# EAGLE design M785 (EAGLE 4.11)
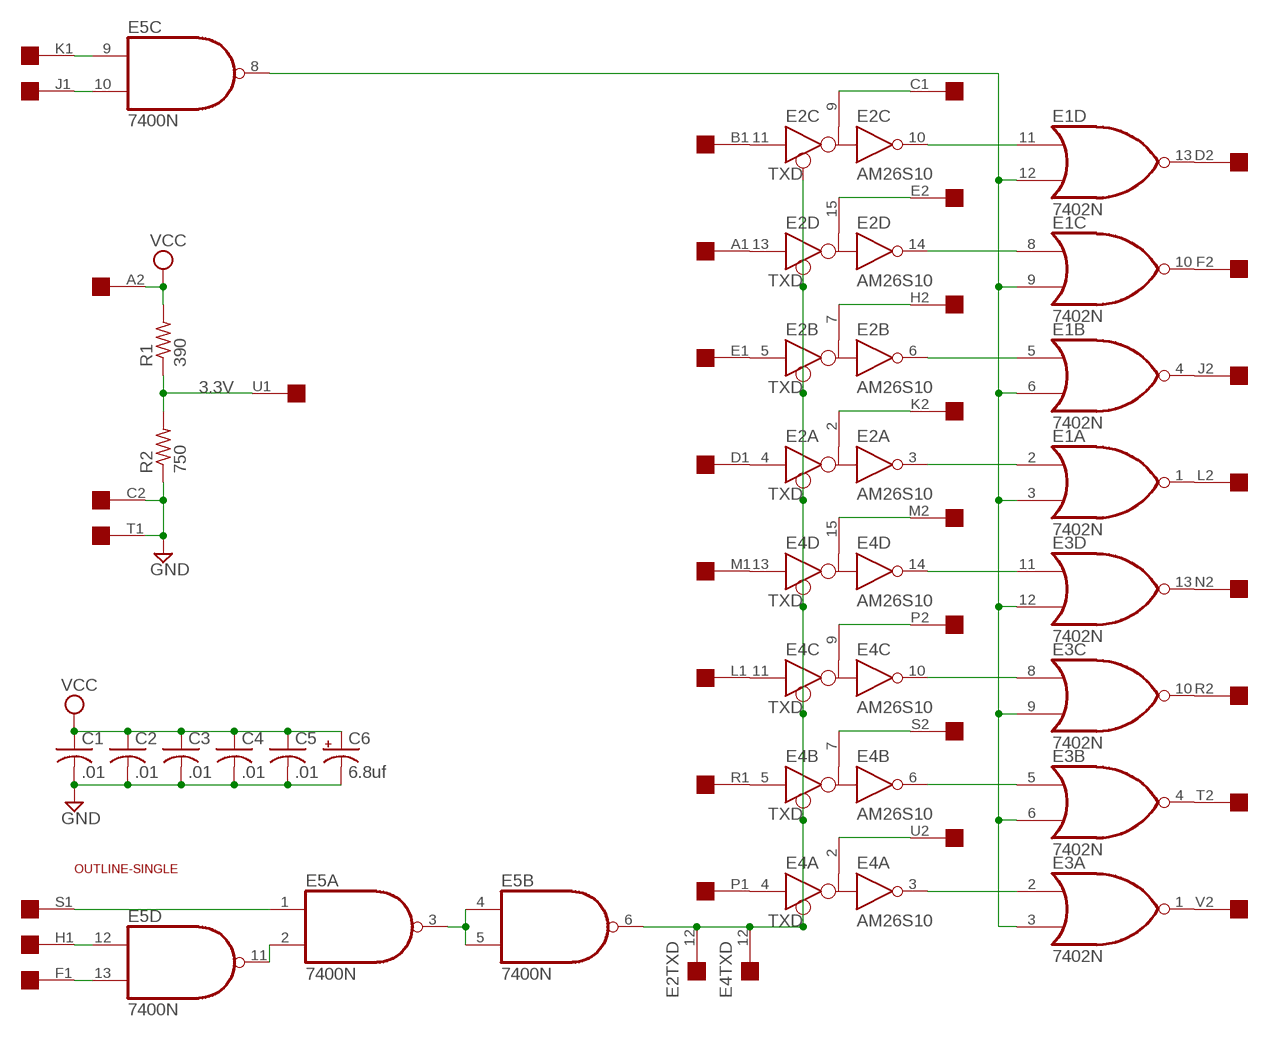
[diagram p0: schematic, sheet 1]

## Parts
C1  .01  C-US050-025X075  [C050-025X075]
C2  .01  C-US050-025X075  [C050-025X075]
C3  .01  C-US050-025X075  [C050-025X075]
C4  .01  C-US050-025X075  [C050-025X075]
C5  .01  C-US050-025X075  [C050-025X075]
C6  6.8uf  CPOL-USE15-5AXIAL  [E15-5]
E1  7402N  [DIL14]
E2  AM26S10  [DIL16]
E3  7402N  [DIL14]
E4  AM26S10  [DIL16]
E5  7400N  [DIL14]
R1  390  R-US_0207/10  [0207/10]
R2  750  R-US_0207/10  [0207/10]
U$1  SINGLE  [EDGE-CON2]
U$2  OUTLINE-SINGLE  [SINGLE]

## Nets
3.3V: R1.1 R2.2 U$1.U1
GND: C1.2 C2.2 C3.2 C4.2 C5.2 C6.- R2.1 U$1.C2 U$1.T1
N$2: E2.12(TXD:TXD) E4.12(TXD:TXD) E5.6(B:O)
N$3: E4.15(D:B) U$1.M2
N$4: E4.9(C:B) U$1.P2
N$5: E4.13(D:D) U$1.M1
N$6: E4.11(C:D) U$1.L1
N$7: E4.7(B:B) U$1.S2
N$8: E4.5(B:D) U$1.R1
N$9: E4.2(A:B) U$1.U2
N$10: E4.4(A:D) U$1.P1
N$11: E2.9(C:B) U$1.C1
N$12: E2.11(C:D) U$1.B1
N$13: E2.15(D:B) U$1.E2
N$14: E2.13(D:D) U$1.A1
N$15: E2.7(B:B) U$1.H2
N$16: E2.5(B:D) U$1.E1
N$17: E2.2(A:B) U$1.K2
N$18: E2.4(A:D) U$1.D1
N$19: E5.9(C:I0) U$1.K1
N$20: E5.10(C:I1) U$1.J1
N$21: E1.13(D:O) U$1.D2
N$22: E1.10(C:O) U$1.F2
N$23: E1.4(B:O) U$1.J2
N$24: E1.1(A:O) U$1.L2
N$25: E3.13(D:O) U$1.N2
N$26: E3.10(C:O) U$1.R2
N$27: E3.4(B:O) U$1.T2
N$28: E3.1(A:O) U$1.V2
N$29: E5.1(A:I0) U$1.S1
N$30: E5.2(A:I1) E5.11(D:O)
N$31: E5.12(D:I0) U$1.H1
N$32: E5.13(D:I1) U$1.F1
N$33: E1.3(A:I1) E1.6(B:I1) E1.9(C:I1) E1.12(D:I1) E3.3(A:I1) E3.6(B:I1) E3.9(C:I1) E3.12(D:I1) E5.8(C:O)
N$34: E3.2(A:I0) E4.3(A:R)
N$35: E3.5(B:I0) E4.6(B:R)
N$36: E3.8(C:I0) E4.10(C:R)
N$37: E3.11(D:I0) E4.14(D:R)
N$38: E1.2(A:I0) E2.3(A:R)
N$39: E1.5(B:I0) E2.6(B:R)
N$40: E1.8(C:I0) E2.14(D:R)
N$41: E1.11(D:I0) E2.10(C:R)
N$42: E5.3(A:O) E5.4(B:I0) E5.5(B:I1)
VCC: C1.1 C2.1 C3.1 C4.1 C5.1 C6.+ R1.2 U$1.A2
Unconnected: U$1.B2 U$1.N1 U$1.V1

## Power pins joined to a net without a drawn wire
GND: E1.7(P:GND) E2.1(GND:GND) E2.8(PWR:GND) E3.7(P:GND) E4.1(GND:GND) E4.8(PWR:GND) E5.7(P:GND)
VCC: E1.14(P:VCC) E2.16(PWR:VCC) E3.14(P:VCC) E4.16(PWR:VCC) E5.14(P:VCC)

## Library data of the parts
C1-C5 = rcl:C-US: CAPACITOR, American symbol
C6 = rcl:CPOL-US: POLARIZED CAPACITOR, American symbol
E1 E3 = 74xx-jameco:74*02: Quad 2-input NOR gate
E2 E4 = dec-con:AM26S10: Bus Transceiver
E5 = 74xx-jameco:74*00: Quad 2-input NAND gate
R1 R2 = rcl:R-US_: RESISTOR, American symbol
U$1 = dec-con:SINGLE: Single-Height DEC board
U$2 = dec-con:OUTLINE-*: Board outlines for DEC boards.

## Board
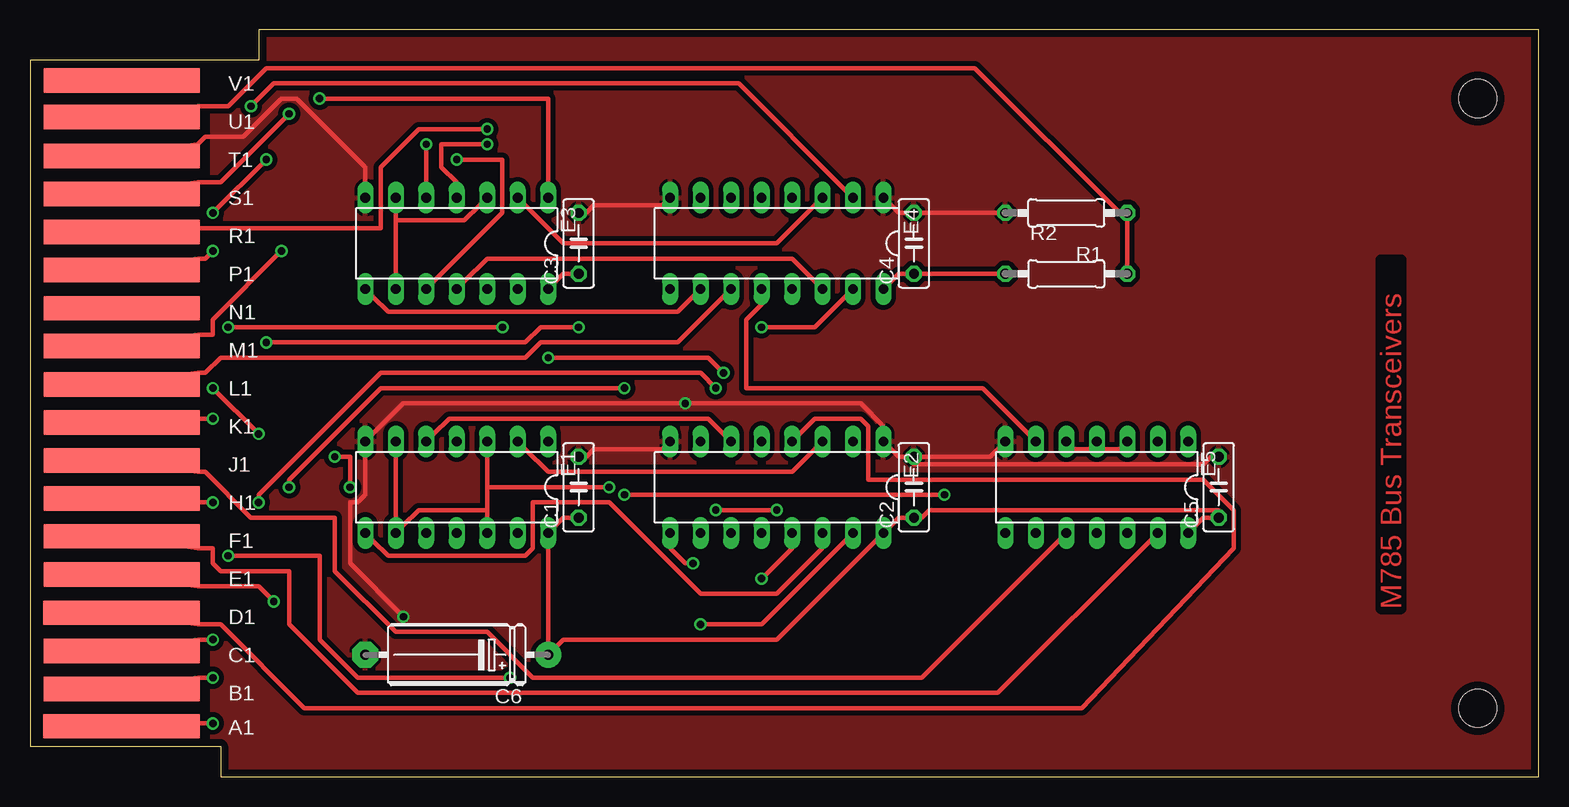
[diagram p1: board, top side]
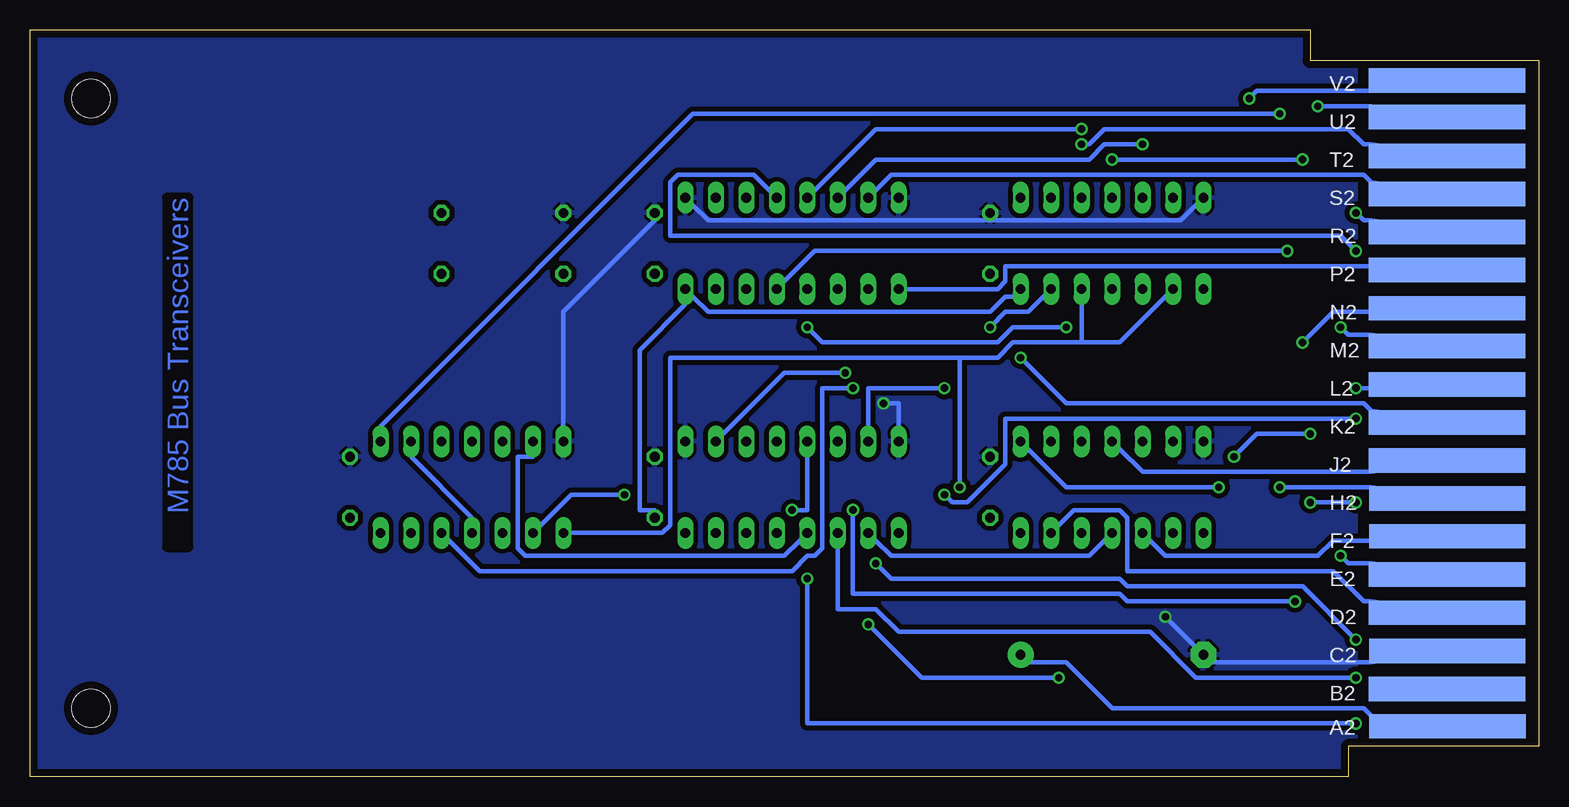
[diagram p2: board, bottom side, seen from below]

Size 125.73 x 62.23 mm. Coordinates in mm from the lower left corner, seen from the top.
Copper layers (1*16): Top 0.035mm / dielectric 1.5mm / Bottom 0.035mm
Design rules "15mils": minimum track width 15mil, minimum drill 24mil, track to track 15mil, track to pad 10mil, pad to pad 10mil, via to via 10mil, smd to smd 10mil, copper to edge 25mil, drill to drill 10mil, minimum pad ring 10mil, minimum via ring 8mil, stop-mask expansion 0mil, vias tented up to drill 0mil, thermal gap 10mil

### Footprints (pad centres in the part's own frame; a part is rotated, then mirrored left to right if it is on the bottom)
C050-025X075 = drill 0.813 octagon: 1 -2.54,0; 2 2.54,0
E15-5 = drill 0.813 pad 2.159 round: + -7.62,0 | drill 0.813 pad 2.159 octagon: - 7.62,0
DIL14 = drill 0.813 long: 1 -7.62,-3.81; 2 -5.08,-3.81; 3 -2.54,-3.81; 4 0,-3.81; 5 2.54,-3.81; 6 5.08,-3.81; 7 7.62,-3.81; 8 7.62,3.81; 9 5.08,3.81; 10 2.54,3.81; 11 0,3.81; 12 -2.54,3.81; 13 -5.08,3.81; 14 -7.62,3.81
DIL16 = drill 0.813 long: 1 -8.89,-3.81; 2 -6.35,-3.81; 3 -3.81,-3.81; 4 -1.27,-3.81; 5 1.27,-3.81; 6 3.81,-3.81; 7 6.35,-3.81; 8 8.89,-3.81; 9 8.89,3.81; 10 6.35,3.81; 11 3.81,3.81; 12 1.27,3.81; 13 -1.27,3.81; 14 -3.81,3.81; 15 -6.35,3.81; 16 -8.89,3.81
0207/10 = drill 0.813 octagon: 1 -5.08,0; 2 5.08,0
EDGE-CON2 = smd 13.017 x 2.032: A1 7.633,4.207; B1 7.639,7.327; C1 7.636,10.489; D1 7.633,13.665; E1 7.642,16.84; F1 7.642,20.041; H1 7.642,23.19; J1 7.642,26.34; K1 7.642,29.515; L1 7.642,32.69; M1 7.642,35.89; N1 7.642,39.04; P1 7.642,42.24; R1 7.642,45.39; S1 7.642,48.565; T1 7.642,51.74; U1 7.642,54.966; V1 7.642,58.026 | smd 13.017 x 2.032 bottom: A2 7.614,4.207; B2 7.642,7.328; C2 7.617,10.49; D2 7.642,13.665; E2 7.642,16.84; F2 7.617,20.041; H2 7.617,23.19; J2 7.642,26.34; K2 7.642,29.515; L2 7.642,32.69; M2 7.642,35.89; N2 7.642,39.04; P2 7.642,42.24; R2 7.642,45.39; S2 7.642,48.565; T2 7.642,51.74; U2 7.642,54.966; V2 7.642,58.026
SINGLE = hole 3.175: 120.65,56.515; 120.65,5.715

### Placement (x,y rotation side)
C1  45.72,24.13 90 top
C2  73.66,24.13 90 top
C3  45.72,44.45 90 top
C4  73.66,44.45 90 top
C5  99.06,24.13 90 top
C6  35.56,10.16 180 top
E1  35.56,24.13 180 top
E2  62.23,24.13 180 top
E3  35.56,44.45 180 top
E4  62.23,44.45 180 top
E5  88.9,24.13 180 top
R1  86.36,41.91 180 top
R2  86.36,46.99 0 top
U$1  0,0 0 top
U$2  0,0 0 top

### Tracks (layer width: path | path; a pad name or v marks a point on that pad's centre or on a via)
3.3V
  Top 0.381: R1.1 91.44,42.55 91.44,46.35 R2.2 90.81,46.99 78.74,59.05 19.69,59.05 16.51,55.88 13.97,55.88 U$1.U1
GND  (via drill 0.61)
  Top 0.381: E4.1 71.76,47.62 72.39,46.99 73.03,46.99 C4.2 74.3,46.99 80.65,46.99 R2.1 | C3.2 46.36,46.99 46.99,47.62 52.71,47.62 E4.8 | U$1.T1 13.97,52.7 14.61,53.34 17.78,53.34 20.96,56.52 22.23,56.52 27.94,50.8 27.94,49.53 E3.7 | C1.2 46.36,26.67 46.99,27.3 52.71,27.3 E2.8 | C2.2 73.03,26.67 72.39,26.67 71.76,27.3 E2.1 71.12,29.21 69.22,31.11 v54.61,31.11 31.12,31.11 28.58,28.57 E1.7 27.94,26.67 27.94,23.5 27.31,22.86 26.67,22.86 26.67,17.78 v31.12,13.34 | E5.7 80.65,27.3 80.01,26.67 74.3,26.67 C2.2 | C5.2 98.43,26.67 97.79,26.04 73.66,26.04 C2.2
  Bottom 0.381: 45.72,46.35 29.85,46.35 28.58,47.62 E3.7 | 45.72,46.35 C3.2 45.72,46.35 | 45.72,46.35 69.22,46.35 70.49,47.62 E4.1 | U$1.C2 13.97,9.53 27.31,9.53 C6.- 28.58,10.79 v31.12,13.34 | v54.61,31.11 53.34,31.11 53.34,29.21 E2.8 | C4.2 73.66,46.35 81.28,38.73 81.28,29.21 E5.7
  pour Bottom (isolate 0.406): 15.24,62.23 125.73,62.23 125.73,0 15.24,0
  pour Top (isolate 0.406): 15.24,62.23 125.73,62.23 125.73,0 15.24,0
N$2
  Top 0.381: E4.12 60.96,39.37 59.69,38.1 59.69,32.38 79.38,32.38 83.19,28.57 E5.6
  Bottom 0.381: E2.12 61.6,19.68 62.87,18.41 84.46,18.41 85.09,19.05 85.09,26.67 83.82,26.67 E5.6
N$3  (via drill 0.61)
  Top 0.381: v60.96,37.47 65.41,37.47 67.95,40.01 E4.15 | v16.51,37.47 v39.37,37.47
  Bottom 0.381: v60.96,37.47 59.69,36.2 45.09,36.2 43.82,37.47 v39.37,37.47 | v16.51,37.47 15.88,36.83 13.97,36.83 U$1.M2
N$4
  Bottom 0.381: E4.9 52.71,40.64 45.09,40.64 44.45,41.27 44.45,42.55 13.97,42.55 U$1.P2
N$5  (via drill 0.61)
  Top 0.381: v20.96,43.81 15.24,38.1 15.24,36.83 13.97,36.83 U$1.M1
  Bottom 0.381: v20.96,43.81 60.33,43.81 62.87,41.27 E4.13
N$6
  Top 0.381: E4.11 57.79,40.01 53.98,36.2 42.55,36.2 41.28,34.92 15.88,34.92 14.61,33.66 13.97,33.66 U$1.L1
N$7
  Bottom 0.381: E4.7 55.25,48.9 53.98,50.16 14.61,50.16 13.97,49.53 U$1.S2
N$8  (via drill 0.61)
  Top 0.381: v38.1,53.98 32.39,53.98 29.21,50.8 29.21,45.72 13.97,45.72 U$1.R1
  Bottom 0.381: v38.1,53.98 55.25,53.98 60.33,48.9 E4.5
N$9  (via drill 0.61)
  Top 0.381: v18.42,55.88 20.32,57.78 59.06,57.78 67.95,48.9 E4.2
  Bottom 0.381: v18.42,55.88 13.97,55.88 U$1.U2
N$10  (via drill 0.61)
  Top 0.381: v15.24,43.81 14.61,43.18 13.97,43.18 U$1.P1
  Bottom 0.381: v15.24,43.81 16.51,45.09 72.39,45.09 72.39,49.53 71.76,50.16 65.41,50.16 64.14,48.9 E4.4
N$11  (via drill 0.61)
  Top 0.381: v55.25,17.78 54.61,17.78 53.34,19.05 E2.9 | v15.24,11.43 13.97,11.43 U$1.C1
  Bottom 0.381: v55.25,17.78 53.98,16.51 34.93,16.51 34.29,15.88 19.69,15.88 v15.24,11.43
N$12  (via drill 0.61)
  Top 0.381: v15.24,8.26 13.97,8.26 U$1.B1
  Bottom 0.381: v15.24,8.26 28.58,8.26 32.39,12.06 53.34,12.06 55.25,13.97 58.42,13.97 58.42,19.05 E2.11
N$13  (via drill 0.61)
  Top 0.381: v55.88,12.7 60.96,12.7 67.95,19.68 E2.15 | v40.01,8.26 27.31,8.26 24.13,11.43 24.13,18.41 v16.51,18.41
  Bottom 0.381: v55.88,12.7 51.44,8.26 v40.01,8.26 | v16.51,18.41 15.88,17.78 13.97,17.78 U$1.E2
N$14  (via drill 0.61)
  Top 0.381: v60.96,16.51 63.5,19.05 E2.13 | v15.24,4.45 13.97,4.45 U$1.A1
  Bottom 0.381: v60.96,16.51 60.96,4.45 v15.24,4.45
N$15  (via drill 0.61)
  Top 0.381: v49.53,32.38 29.21,32.38 21.59,24.77 v21.59,24.13
  Bottom 0.381: v49.53,32.38 55.88,32.38 55.88,29.21 E2.7 | v21.59,24.13 13.97,24.13 U$1.H2
N$16  (via drill 0.61)
  Top 0.381: v57.15,22.23 v62.23,22.23 | v20.32,14.61 19.05,15.88 13.97,15.88 U$1.E1
  Bottom 0.381: v62.23,22.23 60.96,22.23 60.96,26.67 E2.5 | v57.15,22.23 57.15,15.24 34.93,15.24 34.29,14.61 v20.32,14.61
N$17  (via drill 0.61)
  Top 0.381: v57.79,33.66 56.52,34.92 v43.18,34.92
  Bottom 0.381: v57.79,33.66 62.87,33.66 67.95,28.57 E2.2 | v43.18,34.92 39.37,31.11 14.61,31.11 13.97,30.48 U$1.K2
N$18
  Top 0.381: E2.4 64.14,28.57 65.41,29.84 69.22,29.84 69.85,29.21 69.85,24.77 97.79,24.77 100.33,22.23 100.33,19.05 87.63,5.71 22.86,5.71 15.88,12.7 13.97,12.7 U$1.D1
N$19  (via drill 0.61)
  Top 0.381: v49.53,23.5 v76.2,23.5 | v15.24,29.84 13.97,29.84 U$1.K1
  Bottom 0.381: v76.2,23.5 80.65,23.5 83.19,20.95 E5.9 | v49.53,23.5 48.9,22.86 47.63,22.86 44.45,26.04 44.45,29.84 v15.24,29.84
N$20
  Top 0.381: E5.10 85.73,19.68 74.3,8.26 41.91,8.26 38.1,12.06 30.48,12.06 25.4,17.14 25.4,21.59 18.42,21.59 14.61,25.4 13.97,25.4 U$1.J1
N$21
  Bottom 0.381: E1.13 40.01,20.95 38.74,22.23 34.93,22.23 34.29,21.59 34.29,17.14 17.15,17.14 14.61,14.61 13.97,14.61 U$1.D2
N$22
  Bottom 0.381: E1.10 32.39,19.68 31.12,18.41 18.42,18.41 17.15,19.68 13.97,19.68 U$1.F2
N$23
  Bottom 0.381: E1.4 34.93,27.3 33.02,25.4 13.97,25.4 U$1.J2
N$24  (via drill 0.61)
  Top 0.381: v26.67,24.13 26.67,26.67 v25.4,26.67 | v15.24,32.38 v19.05,28.57
  Bottom 0.381: v26.67,24.13 39.37,24.13 42.55,27.3 E1.1 | v25.4,26.67 23.5,28.57 v19.05,28.57 | v15.24,32.38 13.97,32.38 U$1.L2
N$25  (via drill 0.61)
  Top 0.381: v45.72,37.47 42.55,37.47 41.28,36.2 v19.69,36.2
  Bottom 0.381: v45.72,37.47 44.45,38.73 42.55,38.73 41.28,40.01 E3.13 | v19.69,36.2 17.15,38.73 13.97,38.73 U$1.N2
N$26  (via drill 0.61)
  Top 0.381: v35.56,51.44 39.37,51.44 39.37,46.99 33.66,41.27 E3.10 | v15.24,46.99 v19.69,51.44
  Bottom 0.381: v19.69,51.44 v35.56,51.44 | v15.24,46.99 14.61,46.35 13.97,46.35 U$1.R2
N$27  (via drill 0.61)
  Top 0.381: v38.1,52.7 34.29,52.7 34.29,50.8 35.56,49.53 E3.4
  Bottom 0.381: v38.1,52.7 37.47,52.7 36.2,53.98 15.88,53.98 14.61,52.7 13.97,52.7 U$1.T2
N$28  (via drill 0.61)
  Top 0.381: v24.13,56.52 43.18,56.52 43.18,49.53 E3.1
  Bottom 0.381: v24.13,56.52 23.5,57.15 13.97,57.15 U$1.V2
N$29  (via drill 0.61)
  Top 0.381: v21.59,55.24 15.88,49.53 13.97,49.53 U$1.S1
  Bottom 0.381: v21.59,55.24 70.49,55.24 96.52,29.21 E5.1
N$30
  Bottom 0.381: E5.11 88.9,21.59 93.98,26.67 E5.2
N$31  (via drill 0.61)
  Top 0.381: v57.15,32.38 55.88,33.66 29.21,33.66 19.05,23.5 v19.05,22.86 | v15.24,22.86 13.97,22.86 U$1.H1
  Bottom 0.381: v57.15,32.38 59.69,32.38 59.69,19.05 60.33,18.41 60.96,18.41 62.23,17.14 88.27,17.14 90.81,19.68 E5.12 | v15.24,22.86 v19.05,22.86
N$32
  Top 0.381: E5.13 93.35,19.68 80.65,6.99 27.31,6.99 21.59,12.7 21.59,17.14 15.88,17.14 15.24,17.78 15.24,19.05 13.97,19.05 U$1.F1
N$33  (via drill 0.61)
  Top 0.381: E1.6 30.48,26.67 30.48,21.59 E1.9 31.12,20.95 32.39,22.23 38.1,22.23 | 38.1,24.13 38.1,26.67 E1.3 | 38.1,22.23 38.1,24.13 | 38.1,22.23 38.1,21.59 E1.12 | 30.48,46.35 30.48,41.91 E3.9 | 30.48,46.35 30.48,46.99 E3.6 | 30.48,46.35 36.2,46.35 37.47,47.62 E3.3 | 38.1,24.13 v48.26,24.13
  Bottom 0.381: 48.26,34.92 45.09,34.92 43.82,36.2 38.1,36.2 | 48.26,34.92 72.39,34.92 72.39,20.95 73.03,20.32 80.65,20.32 E5.8 | 38.1,36.2 34.93,36.2 31.12,40.01 E3.9 | 38.1,36.2 38.1,39.37 E3.12 | v48.26,24.13 48.26,34.92
N$34
  Top 0.381: E3.2 41.28,47.62 44.45,44.45 62.23,44.45 65.41,47.62 E4.3
N$35  (via drill 0.61)
  Top 0.381: v33.02,52.7 33.02,49.53 E3.5
  Bottom 0.381: v33.02,52.7 36.2,52.7 37.47,51.44 55.25,51.44 57.79,48.9 E4.6
N$36
  Top 0.381: E3.8 28.58,40.01 29.85,38.73 53.98,38.73 55.25,40.01 E4.10
N$37
  Top 0.381: E3.11 36.2,41.27 38.1,43.18 63.5,43.18 65.41,41.27 E4.14
N$38
  Top 0.381: E1.2 41.28,27.3 43.18,25.4 63.5,25.4 65.41,27.3 E2.3
N$39
  Top 0.381: E1.5 33.66,28.57 34.93,29.84 56.52,29.84 57.79,28.57 E2.6
N$40
  Top 0.381: E1.8 28.58,19.68 29.85,18.41 41.28,18.41 41.91,19.05 41.91,22.86 48.26,22.86 55.88,15.24 62.23,15.24 66.04,19.05 E2.14
N$41
  Bottom 0.381: E1.11 36.2,19.68 37.47,18.41 53.98,18.41 55.25,19.68 E2.10
N$42
  Top 0.381: E5.5 87,27.3 88.27,27.3 E5.4 89.54,27.3 90.81,27.3 E5.3
VCC
  Top 0.381: E3.14 43.82,41.27 44.45,41.91 45.09,41.91 C3.1 | E4.16 71.76,41.27 72.39,41.91 73.03,41.91 C4.1 74.3,41.91 80.65,41.91 R1.2 | C1.1 45.09,21.59 44.45,21.59 43.82,20.95 E1.14 43.18,19.05 43.18,10.79 C6.+ 43.82,10.79 44.45,11.43 62.23,11.43 70.49,19.68 E2.16 71.76,20.95 72.39,21.59 73.03,21.59 C2.1 74.3,21.59 74.93,22.23 99.06,22.23 C5.1 98.43,21.59 97.79,21.59 97.16,20.95 E5.14
  Bottom 0.381: E3.14 43.82,40.01 44.45,40.01 45.72,38.73 69.22,38.73 70.49,40.01 E4.16 71.12,39.37 74.93,35.56 74.93,22.23 73.66,22.23 C2.1 | U$1.A2 13.97,5.08 14.61,5.71 35.56,5.71 39.37,9.53 42.55,9.53 C6.+

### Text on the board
Top: M785 Bus Transceivers
Bottom: M785 Bus Transceivers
